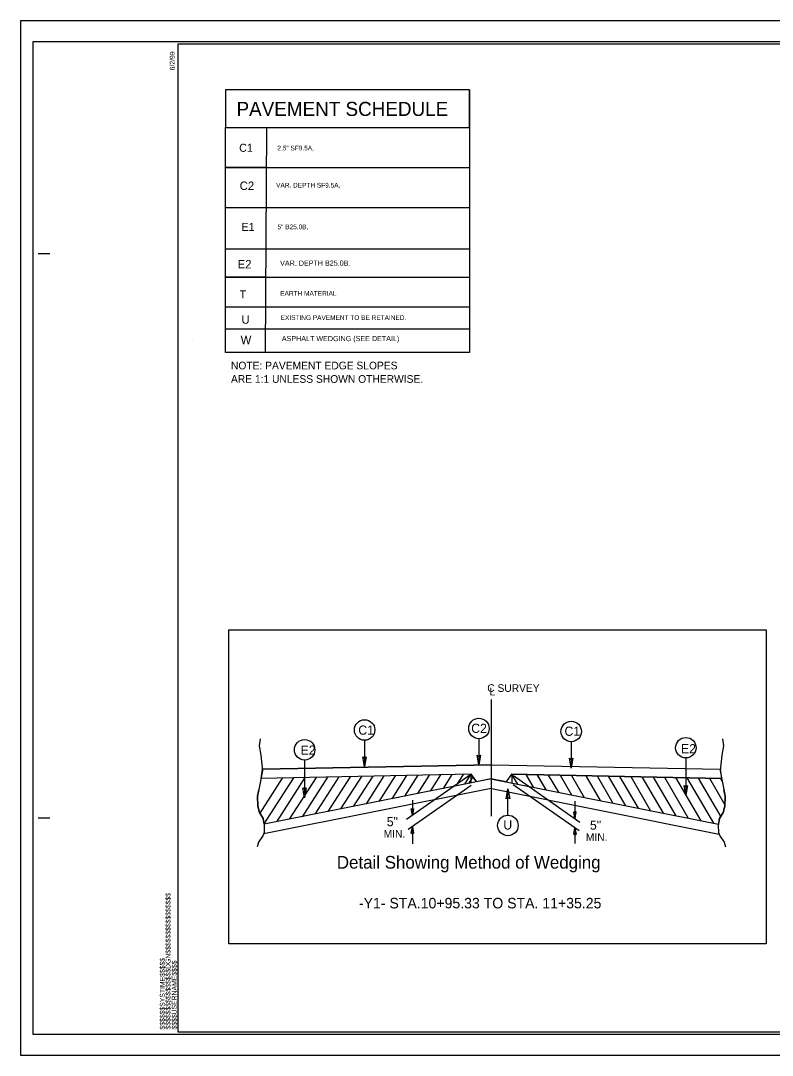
# Model space of a CAD drawing. Extents: x 1818040 to 1825768, y 638918 to 648046.
# Drawn here: x 1820416 to 1821216, y 642603 to 643703 of the extents above; entities that cross this region are included whole.
import ezdxf

# ---------------------------------------------------------------- set-up
doc = ezdxf.new("R2010")
doc.units = 0
for name, color, linetype in [('Old_Level_1', 7, 'Continuous'), ('Prop Pavement Schedule Description CELL', 7, 'Continuous'), ('Sheet Plot Border Inside CELL', 7, 'Continuous'), ('Sheet Plot Border Outside CELL', 7, 'Continuous'), ('Sheet Typical CELL', 7, 'Continuous'), ('Typical Detail Wedge2 CELL', 7, 'Continuous'), ('Typical ID Circle CELL', 7, 'Continuous'), ('Typical Terminator CELL', 7, 'Continuous'), ('Typical Text Centerline CELL', 7, 'Continuous'), ('Typical Text General CELL', 7, 'Continuous'), ('Typical Text Grade Point CELL', 7, 'Continuous'), ('Typical Text ID Circle CELL', 7, 'Continuous')]:
    doc.layers.add(name, color=color, linetype=linetype)

msp = doc.modelspace()

# ---------------------------------------------------------------- linework, layer by layer
at = {"layer": 'Old_Level_1'}
msp.add_lwpolyline([(1820637.6, 643055.8), (1821209.1, 643055.8), (1821209.1, 642721.8), (1820637.6, 642721.8)], close=True, dxfattribs=at)
at = {"layer": 'Prop Pavement Schedule Description CELL'}
for p, q in [((1820893.7, 643629.9), (1820893.7, 643589.8)), ((1820677.8, 643589.8), (1820676.4, 643350.4)), ((1820893.7, 643589.8), (1820893.7, 643504.6)), ((1820893.7, 643516.4), (1820893.7, 643490.9)), ((1820634, 643504.6), (1820893.7, 643504.6)), ((1820634, 643460.8), (1820634, 643504.6)), ((1820893.7, 643504.6), (1820893.7, 643418.2)), ((1820893.7, 643418.2), (1820893.7, 643398.9)), ((1820634, 643398.9), (1820893.7, 643398.9)), ((1820893.7, 643398.9), (1820893.7, 643350.4)), ((1820599.3, 643363.6), (1820599.3, 643363.6))]:
    msp.add_line(p, q, dxfattribs=at)
msp.add_lwpolyline([(1820634, 643589.8), (1820893.7, 643589.8), (1820893.7, 643629.9), (1820634, 643629.9)], close=True, dxfattribs=at)
for points in [[(1820676.6, 643547.2), (1820634, 643547.2), (1820634, 643589.8), (1820893.7, 643589.8)], [(1820634, 643504.6), (1820634, 643547.2), (1820893.7, 643547.2)], [(1820676.6, 643430.7), (1820634, 643430.7), (1820634, 643460.8), (1820893.7, 643460.8)], [(1820634, 643366.7), (1820634, 643430.7), (1820893.7, 643430.7)], [(1820893.7, 643350.4), (1820634, 643350.4), (1820634, 643375.6), (1820893.7, 643375.6)]]:
    msp.add_lwpolyline(points, dxfattribs=at)
at = {"layer": 'Sheet Plot Border Inside CELL'}
msp.add_lwpolyline([(1822095.8, 643680.8), (1820429.3, 643680.8), (1820429.3, 642625.7), (1822095.8, 642625.7)], close=True, dxfattribs=at)
at = {"layer": 'Sheet Plot Border Outside CELL'}
msp.add_lwpolyline([(1822100.3, 643703.3), (1820416.3, 643703.3), (1820416.3, 642603.3), (1822100.3, 642603.3)], close=True, dxfattribs=at)
at = {"layer": 'Sheet Typical CELL'}
for p, q in [((1822100.3, 643703.3), (1820416.3, 643703.3)), ((1820416.3, 643703.3), (1820416.3, 642603.3)), ((1820434.8, 643455.8), (1820447.3, 643455.8)), ((1820434.8, 642855.8), (1820447.3, 642855.8)), ((1820583.3, 642628.3), (1820583.3, 642628.3)), ((1820583.3, 642628.3), (1820583.3, 642628.3)), ((1820583.3, 642628.3), (1820583.3, 642628.3)), ((1820583.3, 642628.3), (1820583.3, 642628.3)), ((1820583.3, 642628.3), (1820583.3, 642628.3)), ((1820583.3, 642628.3), (1820583.3, 642628.3)), ((1820416.3, 642603.3), (1822100.3, 642603.3))]:
    msp.add_line(p, q, dxfattribs=at)
msp.add_lwpolyline([(1822083.3, 643678.3), (1820583.3, 643678.3), (1820583.3, 642628.3), (1822083.3, 642628.3)], close=True, dxfattribs=at)
msp.add_lwpolyline([(1820620.8, 642628.3), (1820620.8, 642628.3)], dxfattribs=at)
at = {"layer": 'Typical Detail Wedge2 CELL'}
for p, q in [((1820916.9, 642857.5), (1820916.9, 642981.5)), ((1820671.1, 642939.6), (1820669.8, 642932.4)), ((1820916.9, 642857.5), (1820916.9, 642942.2)), ((1820669.8, 642932.4), (1820671.8, 642922.3)), ((1820671.8, 642922.3), (1820673.5, 642905.9)), ((1820672, 642897.6), (1820673.4, 642907.4)), ((1820916.9, 642912.3), (1820673.4, 642907.4)), ((1820673.4, 642907.4), (1820916.9, 642912.3)), ((1820916.9, 642912.3), (1821160.4, 642907.4)), ((1820916.9, 642912.3), (1821160.4, 642907.4)), ((1821160.4, 642907.4), (1821161.8, 642897.6)), ((1820694.4, 642898.1), (1820670.6, 642860.9)), ((1820673.5, 642905.9), (1820671.1, 642892.9)), ((1820895.5, 642902.1), (1820672, 642897.6)), ((1820895.5, 642902.1), (1820672, 642897.6)), ((1820706.5, 642898.3), (1820675.1, 642849.4)), ((1820917.2, 642897.3), (1820675.2, 642848.9)), ((1820718.5, 642898.6), (1820688.4, 642851.5)), ((1820730.5, 642898.8), (1820702, 642854.3)), ((1820742.6, 642899.1), (1820715.6, 642857)), ((1820754.6, 642899.3), (1820729.2, 642859.7)), ((1820766.6, 642899.5), (1820742.9, 642862.4)), ((1820778.7, 642899.8), (1820756.5, 642865.2)), ((1820790.7, 642900), (1820770.1, 642867.9)), ((1820802.7, 642900.3), (1820783.7, 642870.6)), ((1820814.7, 642900.5), (1820797.3, 642873.3)), ((1820826.8, 642900.7), (1820811, 642876.1)), ((1820838.8, 642901), (1820824.6, 642878.8)), ((1820895.2, 642901.9), (1820826.6, 642853.9)), ((1820850.8, 642901.2), (1820838.2, 642881.5)), ((1820862.9, 642901.5), (1820851.8, 642884.2)), ((1820874.9, 642901.7), (1820865.5, 642887)), ((1820886.9, 642901.9), (1820879.1, 642889.7)), ((1820888.6, 642891.7), (1820895.2, 642902)), ((1820897.3, 642899.5), (1820892.7, 642892.4)), ((1820895.2, 642902), (1820895.2, 642893.5)), ((1820901, 642894.1), (1820895.5, 642902.1)), ((1820895.5, 642901.9), (1820901, 642894.1)), ((1820916.5, 642897.3), (1820901, 642894.1)), ((1820916.5, 642897.3), (1821158.6, 642848.9)), ((1820932.8, 642894.1), (1820916.5, 642897.3)), ((1820938.4, 642902.1), (1820932.8, 642894.1)), ((1820938.4, 642902.1), (1820932.8, 642894.1)), ((1820938.1, 642901.9), (1820938.4, 642901.9)), ((1820938.4, 642902.1), (1821161.8, 642897.6)), ((1821161.8, 642897.6), (1820938.4, 642902.1)), ((1820945.2, 642891.7), (1820938.6, 642902)), ((1820938.6, 642902), (1820938.6, 642892.7)), ((1820940.3, 642900.8), (1821011, 642851.3)), ((1820953.6, 642901.8), (1820961.5, 642888.3)), ((1820965.6, 642901.6), (1820974.9, 642885.6)), ((1820965.8, 642901.3), (1820974.9, 642885.7)), ((1820977.5, 642901.3), (1820988.3, 642883)), ((1820990, 642901.1), (1821002.2, 642880.1)), ((1821002.1, 642900.8), (1821015.7, 642877.5)), ((1821017.3, 642900.5), (1821032.8, 642874.1)), ((1821029.3, 642900.3), (1821046.1, 642871.4)), ((1821041.2, 642900.1), (1821059.5, 642868.7)), ((1821053.2, 642899.8), (1821072.9, 642866)), ((1821065.1, 642899.6), (1821086.2, 642863.4)), ((1821077.1, 642899.3), (1821099.6, 642860.7)), ((1821089, 642899.1), (1821113, 642858)), ((1821101, 642898.9), (1821126.3, 642855.3)), ((1821112.9, 642898.6), (1821139.7, 642852.7)), ((1821124.9, 642898.4), (1821153.1, 642850)), ((1821136.8, 642898.1), (1821160.8, 642857)), ((1821148.8, 642897.9), (1821165.3, 642869.6)), ((1821160.7, 642897.7), (1821162.2, 642895.1)), ((1820671.1, 642892.9), (1820668.3, 642878.9)), ((1820916.8, 642886.9), (1820675.1, 642838.6)), ((1820895.4, 642890.2), (1820828.3, 642843.2)), ((1820917, 642886.9), (1821159.2, 642838.4)), ((1820940.2, 642891.2), (1821010.2, 642842.2)), ((1820668.3, 642878.9), (1820668.5, 642868.3)), ((1820818, 642877.5), (1820810.4, 642875.9)), ((1820832.9, 642874.6), (1820832.9, 642858.3)), ((1821005.8, 642873.6), (1821005.8, 642854.9)), ((1820668.5, 642868.3), (1820670.3, 642861.6)), ((1820832.9, 642858.3), (1820831.6, 642865.4)), ((1820832.9, 642864.5), (1820831.6, 642865.4)), ((1820832.9, 642858.3), (1820831.8, 642865.3)), ((1820832, 642865.2), (1820832.9, 642858.3)), ((1820832.9, 642858.3), (1820832.2, 642865)), ((1820832.3, 642864.9), (1820832.9, 642858.3)), ((1820832.9, 642858.3), (1820832.5, 642864.8)), ((1820832.7, 642864.6), (1820832.9, 642858.3)), ((1820832.9, 642858.3), (1820834.2, 642865.4)), ((1820834.2, 642865.4), (1820832.9, 642864.5)), ((1820834, 642865.3), (1820832.9, 642858.3)), ((1820832.9, 642858.3), (1820833.8, 642865.2)), ((1820833.6, 642865), (1820832.9, 642858.3)), ((1820832.9, 642858.3), (1820833.4, 642864.9)), ((1820833.2, 642864.8), (1820832.9, 642858.3)), ((1820832.9, 642858.3), (1820833.1, 642864.6)), ((1820832.9, 642864.5), (1820832.9, 642858.3)), ((1821005.8, 642854.9), (1821004.5, 642862.1)), ((1821005.8, 642861.2), (1821004.5, 642862.1)), ((1821005.8, 642854.9), (1821007.1, 642862.1)), ((1821007.1, 642862.1), (1821005.8, 642861.2)), ((1820670.3, 642861.6), (1820674.1, 642854.9)), ((1820674.1, 642854.9), (1820675.4, 642847.6)), ((1821005.8, 642854.9), (1821004.7, 642862)), ((1821004.9, 642861.8), (1821005.8, 642854.9)), ((1821005.8, 642854.9), (1821005.1, 642861.7)), ((1821005.3, 642861.6), (1821005.8, 642854.9)), ((1821005.8, 642854.9), (1821005.4, 642861.4)), ((1821005.6, 642861.3), (1821005.8, 642854.9)), ((1821006.9, 642862), (1821005.8, 642854.9)), ((1821005.8, 642854.9), (1821006.7, 642861.8)), ((1821006.5, 642861.7), (1821005.8, 642854.9)), ((1821005.8, 642854.9), (1821006.3, 642861.6)), ((1821006.2, 642861.4), (1821005.8, 642854.9)), ((1821005.8, 642854.9), (1821006, 642861.3)), ((1821005.8, 642861.2), (1821005.8, 642854.9)), ((1820675.2, 642840.2), (1820673.9, 642836.7)), ((1820675.4, 642847.6), (1820675.2, 642840.2)), ((1820832.9, 642846.4), (1820831.6, 642839.3)), ((1820831.6, 642839.3), (1820832.9, 642840.2)), ((1820831.8, 642839.4), (1820832.9, 642846.4)), ((1820832.9, 642846.4), (1820832, 642839.5)), ((1820832.2, 642839.7), (1820832.9, 642846.4)), ((1820832.9, 642846.4), (1820832.3, 642839.8)), ((1820832.5, 642839.9), (1820832.9, 642846.4)), ((1820832.9, 642846.4), (1820832.7, 642840.1)), ((1820832.9, 642846.4), (1820832.9, 642828)), ((1820832.9, 642846.4), (1820834.2, 642839.3)), ((1820832.9, 642840.2), (1820832.9, 642846.4)), ((1820833.1, 642840.1), (1820832.9, 642846.4)), ((1820832.9, 642846.4), (1820833.2, 642839.9)), ((1820833.4, 642839.8), (1820832.9, 642846.4)), ((1820832.9, 642846.4), (1820833.6, 642839.7)), ((1820833.8, 642839.5), (1820832.9, 642846.4)), ((1820832.9, 642846.4), (1820834, 642839.4)), ((1820832.9, 642840.2), (1820834.2, 642839.3)), ((1821005.8, 642845.3), (1821004.5, 642838.1)), ((1821004.7, 642838.2), (1821005.8, 642845.3)), ((1821005.8, 642845.3), (1821004.9, 642838.4)), ((1821005.1, 642838.5), (1821005.8, 642845.3)), ((1821005.8, 642845.3), (1821005.3, 642838.6)), ((1821005.4, 642838.8), (1821005.8, 642845.3)), ((1821005.8, 642845.3), (1821005.6, 642838.9)), ((1821005.8, 642845.3), (1821005.8, 642828.5)), ((1821005.8, 642845.3), (1821007.1, 642838.1)), ((1821005.8, 642839), (1821005.8, 642845.3)), ((1821006, 642838.9), (1821005.8, 642845.3)), ((1821005.8, 642845.3), (1821006.2, 642838.8)), ((1821006.3, 642838.6), (1821005.8, 642845.3)), ((1821005.8, 642845.3), (1821006.5, 642838.5)), ((1821006.7, 642838.4), (1821005.8, 642845.3)), ((1821005.8, 642845.3), (1821006.9, 642838.2)), ((1820669.4, 642829.8), (1820667.9, 642825.1)), ((1820673.9, 642836.7), (1820669.4, 642829.8)), ((1821004.5, 642838.1), (1821005.8, 642839)), ((1821005.8, 642839), (1821007.1, 642838.1))]:
    msp.add_line(p, q, dxfattribs=at)
for points in [[(1821162.6, 642939.6), (1821163.9, 642932.4), (1821162, 642922.3), (1821160.3, 642905.9), (1821162.6, 642892.9), (1821165.5, 642878.9), (1821165.2, 642868.3), (1821163.5, 642861.6), (1821159.6, 642854.9), (1821158.3, 642847.6), (1821158.5, 642840.2), (1821159.8, 642836.7), (1821164.4, 642829.8), (1821165.9, 642825.1)], [(1820675.2, 642848.9), (1820674.1, 642854.9), (1820670.3, 642861.6), (1820668.5, 642868.3), (1820668.3, 642878.9), (1820669.6, 642885.4)], [(1821158.6, 642848.9), (1821159.6, 642854.9), (1821163.5, 642861.6), (1821165.2, 642868.3), (1821165.5, 642878.9), (1821164.1, 642885.4)]]:
    msp.add_lwpolyline(points, dxfattribs=at)
at = {"layer": 'Typical ID Circle CELL'}
for p, q in [((1820903.7, 642939.9), (1820903.7, 642911.8)), ((1820782.1, 642938.3), (1820782.1, 642910.2)), ((1821001.8, 642936.7), (1821001.8, 642908.6)), ((1820718.3, 642917.2), (1820718.3, 642877.2)), ((1821123.8, 642919.4), (1821123.8, 642879.5)), ((1820934.5, 642858.6), (1820934.5, 642886.7))]:
    msp.add_line(p, q, dxfattribs=at)
for centre in [(1820903.7, 642950.8), (1820782.1, 642949.2), (1821001.8, 642947.6), (1821123.8, 642930.3), (1820718.3, 642928.1), (1820934.5, 642847.7)]:
    msp.add_circle(centre, 10.9, dxfattribs=at)
at = {"layer": 'Typical Terminator CELL'}
for points in [[(1820783.9, 642920.8), (1820782.1, 642910.2), (1820780.2, 642920.8), (1820782.1, 642919.5)], [(1820783.9, 642920.8), (1820782.1, 642910.2), (1820780.2, 642920.8), (1820782.1, 642919.5)], [(1820905.5, 642922.3), (1820903.7, 642911.8), (1820901.8, 642922.4), (1820903.7, 642921)], [(1820905.5, 642922.3), (1820903.7, 642911.8), (1820901.8, 642922.4), (1820903.7, 642921)], [(1821003.6, 642919.2), (1821001.8, 642908.6), (1820999.9, 642919.2), (1821001.8, 642917.9)], [(1820720.1, 642887.8), (1820718.3, 642877.2), (1820716.4, 642887.8), (1820718.3, 642886.5)], [(1820720.1, 642887.8), (1820718.3, 642877.2), (1820716.4, 642887.8), (1820718.3, 642886.5)], [(1820932.7, 642876.1), (1820934.5, 642886.7), (1820936.4, 642876.1), (1820934.5, 642877.4)], [(1820932.7, 642876.1), (1820934.5, 642886.7), (1820936.4, 642876.1), (1820934.5, 642877.4)], [(1821125.6, 642890), (1821123.8, 642879.5), (1821121.9, 642890.1), (1821123.8, 642888.7)]]:
    msp.add_lwpolyline(points, close=True, dxfattribs=at)

# ---------------------------------------------------------------- texts
at = {"layer": 'Prop Pavement Schedule Description CELL'}
for s, height, p in [('PAVEMENT SCHEDULE', 15, (1820645.9, 643602)), ('C1', 8.51, (1820648.7, 643563.9)), (' 2.5" SF9.5A, ', 5, (1820687.4, 643565.4)), ('C2', 8.98, (1820649.3, 643523.3)), (' VAR. DEPTH SF9.5A, ', 5, (1820686.1, 643525.9)), ('E1', 8.51, (1820651.2, 643479.8)), (' 5" B25.0B, ', 5, (1820687.6, 643481.6)), ('E2', 8.98, (1820647.1, 643439.9)), ('VAR. DEPTH B25.0B.', 5.5, (1820692.3, 643442.8)), ('T', 8.51, (1820649.3, 643408.1)), ('EARTH MATERIAL ', 5, (1820692.4, 643410.9)), ('U', 8.98, (1820651.2, 643381.1)), ('EXISTING PAVEMENT TO BE RETAINED.', 5, (1820692.9, 643385.1)), ('W', 8.98, (1820650.3, 643359.3)), ('ASPHALT WEDGING (SEE DETAIL)', 5.5, (1820694.1, 643362.6)), ('NOTE: PAVEMENT EDGE SLOPES ', 8.162, (1820640, 643332.6)), ('ARE 1:1 UNLESS SHOWN OTHERWISE.', 8.162, (1820640, 643318.3))]:
    msp.add_text(s, height=height, dxfattribs=at).set_placement(p)
at = {"layer": 'Sheet Typical CELL'}
for s, p in [('6/2/99', (1820580.2, 643650.5)), ('$$$$$$$$$$$$$$$$DGN$$$$$$$$$$$$$$$$', (1820575.7, 642630.7)), ('$$$$$$SYSTIME$$$$$', (1820569.6, 642630.7)), ('$$$$USERNAME$$$$', (1820582.3, 642630.7))]:
    msp.add_text(s, height=5.25, rotation=90, dxfattribs=at).set_placement(p)
at = {"layer": 'Typical Detail Wedge2 CELL'}
for s, height, p in [('5"', 9.73, (1820805.7, 642846.8)), ('5"', 9.73, (1821021.8, 642843.2)), ('MIN.', 8.13, (1820802.4, 642834.8)), ('MIN.', 8.13, (1821017.4, 642831.3))]:
    msp.add_text(s, height=height, dxfattribs=at).set_placement(p)
at = {"layer": 'Typical Text Centerline CELL'}
for s, p in [('C SURVEY ', (1820912.6, 642989.7)), ('L', (1820915, 642985.9))]:
    msp.add_text(s, height=8.13, dxfattribs=at).set_placement(p)
at = {"layer": 'Typical Text General CELL'}
msp.add_text('Detail Showing Method of Wedging', height=13.428, dxfattribs=at).set_placement((1820752.6, 642801.8))
at = {"layer": 'Typical Text Grade Point CELL'}
msp.add_text('-Y1- STA.10+95.33 TO STA. 11+35.25', height=11.19, dxfattribs=at).set_placement((1820776.1, 642759.5))
at = {"layer": 'Typical Text ID Circle CELL'}
for s, p in [('C1', (1820775.4, 642944.2)), ('C2', (1820895.5, 642946.1)), ('C1', (1820994.7, 642943)), ('E2', (1820714.1, 642922.9)), ('E2', (1821118.6, 642924.4)), ('U', (1820929.7, 642843.4))]:
    msp.add_text(s, height=9.73, dxfattribs=at).set_placement(p)

doc.saveas('drawing.dxf')
